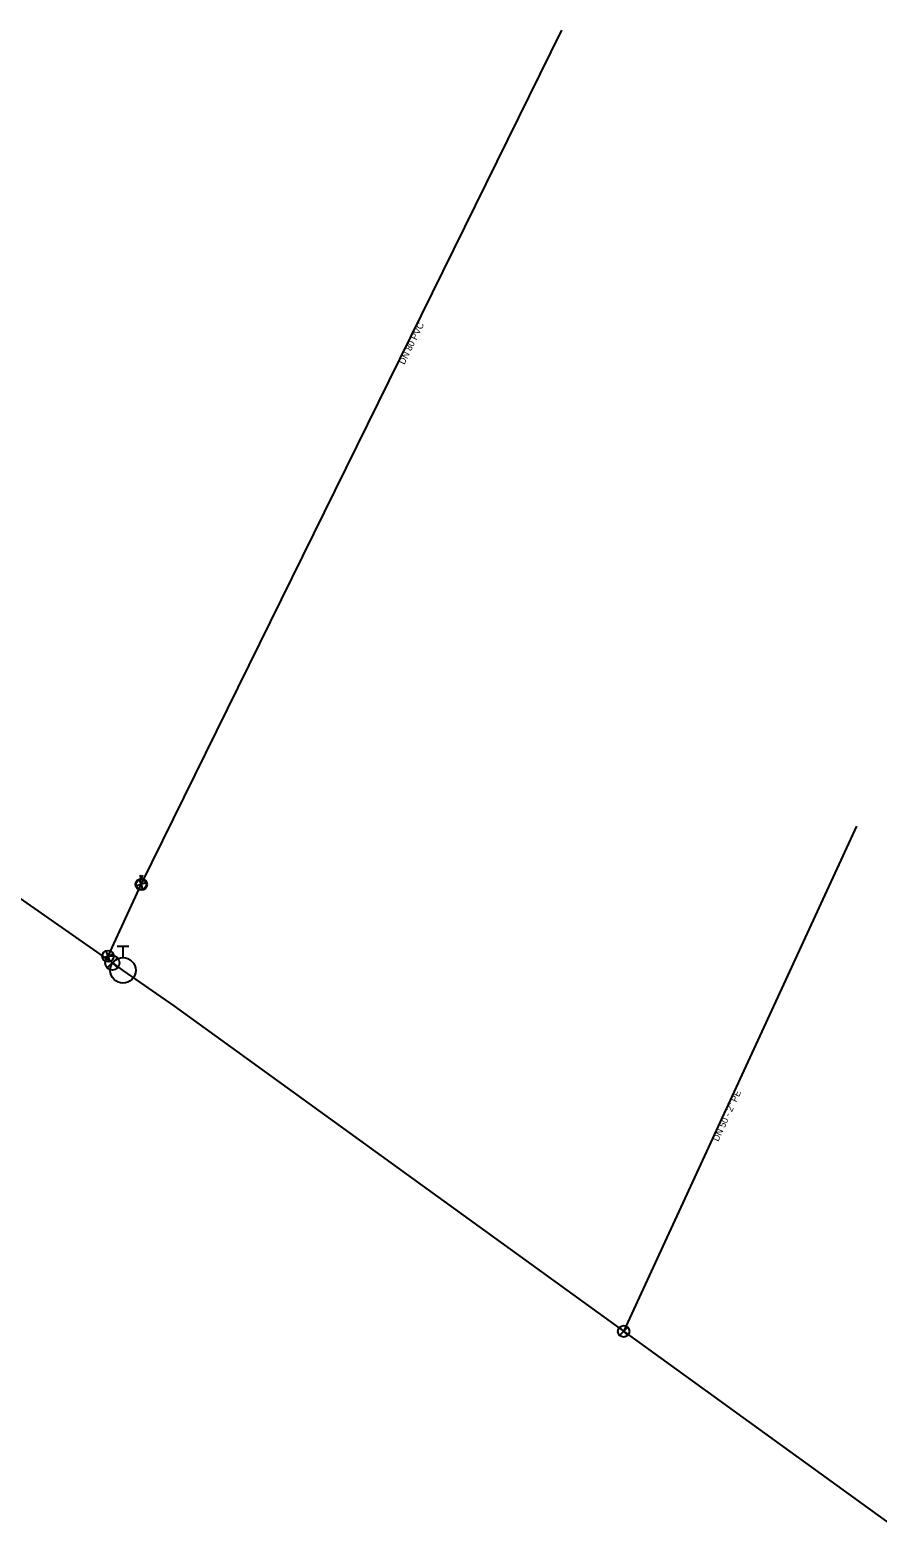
# Model space of a CAD drawing. Extents: x -482851 to -482354, y -1127969 to -1127406.
# Drawn here: x -482757.7 to -482698.8, y -1127510.7 to -1127406 of the extents above; entities that cross this region are included whole.
import ezdxf

# ---------------------------------------------------------------- set-up
doc = ezdxf.new("R2010")
doc.units = 0
for name, color, linetype in [('_pripojka_prevzato_z_dokumentace_', 7, 'Continuous'), ('_pripojka_priblizne_', 7, 'Continuous'), ('_voda_smvak_prevzato_z_dokumentace_', 7, 'Continuous'), ('Default', 7, 'Continuous'), ('MoLevel 27', 7, 'Continuous'), ('MoLevel 28', 7, 'Continuous'), ('MoLevel 30', 7, 'Continuous'), ('MoLevel 32', 7, 'Continuous'), ('MoLevel 53', 7, 'Continuous'), ('MoLevel 55', 7, 'Continuous')]:
    doc.layers.add(name, color=color, linetype=linetype)

# ---------------------------------------------------------------- blocks, each defined once
blk = doc.blocks.new('_uzaver_')
at = {"layer": 'Default'}
for p, q in [((-0.000035, -0.000035), (0.000035, 0.000035)), ((0.000035, -0.000035), (-0.000035, 0.000035))]:
    blk.add_line(p, q, dxfattribs=at)
for radius in [0.00005, 0.0000025]:
    blk.add_circle((0, 0), radius, dxfattribs=at)
blk = doc.blocks.new('_uzaver_pripojka_')
at = {"layer": 'Default'}
for p, q in [((-0.000035, -0.000035), (0.000035, 0.000035)), ((0.000035, -0.000035), (-0.000035, 0.000035))]:
    blk.add_line(p, q, dxfattribs=at)
for radius in [0.00005, 0.0000025]:
    blk.add_circle((0, 0), radius, dxfattribs=at)
blk = doc.blocks.new('_hydrant_voda_')
at = {"layer": 'Default'}
for p, q in [((-0.0000225, 0.000095), (0.0000225, 0.000095)), ((0, 0.000095), (0, 0.00005))]:
    blk.add_line(p, q, dxfattribs=at)
blk.add_circle((0, 0), 0.00005, dxfattribs=at)
blk = doc.blocks.new('_sachta_voda_')
at = {"layer": 'Default'}
blk.add_lwpolyline([(-0.00001, 0.000065), (0, 0.000035), (0.00001, 0.000065)], dxfattribs=at)
blk.add_circle((0, 0), 0.000035, dxfattribs=at)

msp = doc.modelspace()

# ---------------------------------------------------------------- linework, layer by layer
at = {"layer": '_pripojka_prevzato_z_dokumentace_'}
for p, q in [((-482750, -1127465.28), (-482720.79, -1127405.95)), ((-482752.31, -1127470.26), (-482750, -1127465.28)), ((-482752.41, -1127470.45), (-482752.31, -1127470.26))]:
    msp.add_line(p, q, dxfattribs=at)
at = {"layer": '_pripojka_priblizne_'}
msp.add_line((-482716.49, -1127496.32), (-482700.29, -1127461.23), dxfattribs=at)
at = {"layer": '_voda_smvak_prevzato_z_dokumentace_'}
for p, q in [((-482752.41, -1127470.45), (-482752.01, -1127470.73)), ((-482752.01, -1127470.73), (-482751.27, -1127471.25))]:
    msp.add_line(p, q, dxfattribs=at)
for points in [[(-482824.9, -1127421.84), (-482824.71, -1127421.96), (-482817.61, -1127424.7), (-482812.09, -1127429.62), (-482780.51, -1127450.85), (-482752.65, -1127470.28), (-482752.41, -1127470.45)], [(-482751.27, -1127471.25), (-482747.73, -1127473.71), (-482696.67, -1127510.66)]]:
    msp.add_lwpolyline(points, dxfattribs=at)

# ---------------------------------------------------------------- block references
at = {"layer": 'MoLevel 27', "xscale": 10000, "yscale": 10000}
msp.add_blockref('_uzaver_', (-482752.01, -1127470.73), dxfattribs=at)
at = {"layer": 'MoLevel 28', "xscale": 17636.68430335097, "yscale": 17636.68430335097}
msp.add_blockref('_hydrant_voda_', (-482751.27, -1127471.25), dxfattribs=at)
at = {"layer": 'MoLevel 30', "xscale": 10000, "yscale": 10000}
msp.add_blockref('_sachta_voda_', (-482750, -1127465.28), dxfattribs=at)
at = {"layer": 'MoLevel 53'}
for p, xscale, yscale, rotation in [((-482750, -1127465.28), 8000, 7999.999999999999, 63.7702982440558), ((-482752.31, -1127470.26), 7999.999999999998, 8000, 65.4939599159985)]:
    msp.add_blockref('_uzaver_pripojka_', p, dxfattribs=dict(at, xscale=xscale, yscale=yscale, rotation=rotation))
at = {"layer": 'MoLevel 53', "xscale": 7999.999999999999, "yscale": 7999.999999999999}
msp.add_blockref('_uzaver_pripojka_', (-482716.49, -1127496.32), dxfattribs=at)

# ---------------------------------------------------------------- texts
at = {"layer": 'MoLevel 32'}
msp.add_text("DN 50 - 2'' PE", height=0.455, rotation=65.2197, dxfattribs=at).set_placement((-482709.92, -1127483.17))
at = {"layer": 'MoLevel 55'}
msp.add_text('DN 80 PVC', height=0.455, rotation=63.7906, dxfattribs=at).set_placement((-482731.73, -1127429.21))

doc.saveas('drawing.dxf')
